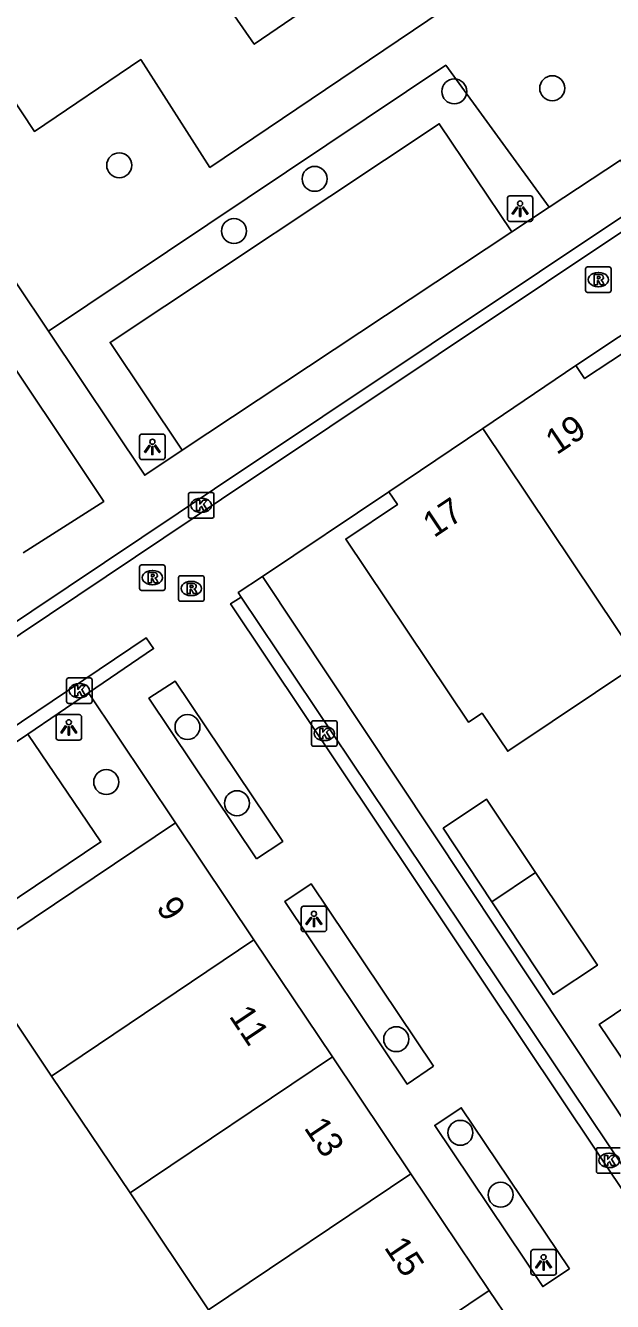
# Model space of a CAD drawing. Extents: x 158797 to 159887, y 384318 to 385255.
# Drawn here: x 159170.3 to 159193.3, y 384529.2 to 384579.2 of the extents above; entities that cross this region are included whole.
import ezdxf

# ---------------------------------------------------------------- set-up
doc = ezdxf.new("R2010")
doc.units = 0
for name, color, linetype in [('IMGEO_Boom', 7, 'Continuous'), ('IMGEO_Groenvoorziening', 7, 'Continuous'), ('IMGEO_Haag', 7, 'Continuous'), ('IMGEO_Kolk', 7, 'Continuous'), ('IMGEO_Lichtpunt', 7, 'Continuous'), ('IMGEO_Pand', 7, 'Continuous'), ('IMGEO_Pand_nummerreeks', 7, 'Continuous'), ('IMGEO_Parkeervlak_open', 7, 'Continuous'), ('IMGEO_Rijbaan_lokaal_open', 7, 'Continuous'), ('IMGEO_Rioolput', 7, 'Continuous'), ('IMGEO_Voetpad_gesloten', 7, 'Continuous'), ('IMGEO_Voetpad_open', 7, 'Continuous')]:
    doc.layers.add(name, color=color, linetype=linetype)

msp = doc.modelspace()

# ---------------------------------------------------------------- linework, layer by layer
at = {"layer": 'IMGEO_Boom'}
for centre in [(159187.135, 384576.663), (159190.976, 384576.789), (159174.003, 384573.767), (159181.664, 384573.236), (159178.503, 384571.191), (159176.68, 384551.749), (159173.494, 384549.591), (159178.62, 384548.763), (159184.861, 384539.513), (159187.378, 384535.843), (159188.951, 384533.417)]:
    msp.add_circle(centre, 0.489, dxfattribs=at)
at = {"layer": 'IMGEO_Groenvoorziening'}
msp.add_lwpolyline([(159179.615, 384557.65), (159196.883, 384531.677)], dxfattribs=at)
at = {"layer": 'IMGEO_Haag'}
msp.add_lwpolyline([(159171.232, 384567.261), (159186.801, 384577.691), (159190.856, 384572.121)], dxfattribs=at)
at = {"layer": 'IMGEO_Kolk'}
for p, q in [((159176.716, 384560.013), (159176.716, 384560.865)), ((159176.791, 384560.939), (159177.643, 384560.939)), ((159177.204, 384560.719), (159177.229, 384560.719)), ((159177.717, 384560.865), (159177.717, 384560.013)), ((159177.227, 384560.159), (159177.202, 384560.159)), ((159177.643, 384559.939), (159176.791, 384559.939)), ((159171.941, 384552.748), (159171.941, 384553.6)), ((159172.016, 384553.674), (159172.868, 384553.674)), ((159172.942, 384553.6), (159172.942, 384552.748)), ((159172.429, 384553.454), (159172.454, 384553.454)), ((159172.868, 384552.674), (159172.016, 384552.674)), ((159172.452, 384552.894), (159172.427, 384552.894)), ((159181.617, 384551.995), (159182.469, 384551.995)), ((159181.542, 384551.069), (159181.542, 384551.921)), ((159182.03, 384551.775), (159182.055, 384551.775)), ((159182.543, 384551.921), (159182.543, 384551.069)), ((159182.469, 384550.995), (159181.617, 384550.995)), ((159182.053, 384551.215), (159182.028, 384551.215)), ((159192.708, 384534.334), (159192.708, 384535.186)), ((159192.783, 384535.26), (159193.635, 384535.26)), ((159193.196, 384535.04), (159193.221, 384535.04)), ((159193.635, 384534.26), (159192.783, 384534.26)), ((159193.219, 384534.48), (159193.194, 384534.48))]:
    msp.add_line(p, q, dxfattribs=at)
for points in [[(159176.716, 384560.013), (159176.716, 384560.865)], [(159176.791, 384560.939), (159177.643, 384560.939)], [(159177.037, 384560.639), (159177.16, 384560.639), (159177.16, 384560.488), (159177.29, 384560.639), (159177.454, 384560.639), (159177.308, 384560.488), (159177.461, 384560.239), (159177.309, 384560.239), (159177.224, 384560.403), (159177.16, 384560.336), (159177.16, 384560.239), (159177.037, 384560.239), (159177.037, 384560.639)], [(159177.717, 384560.865), (159177.717, 384560.013)], [(159177.643, 384559.939), (159176.791, 384559.939)], [(159171.941, 384552.748), (159171.941, 384553.6)], [(159172.016, 384553.674), (159172.868, 384553.674)], [(159172.942, 384553.6), (159172.942, 384552.748)], [(159172.262, 384553.374), (159172.385, 384553.374), (159172.385, 384553.223), (159172.515, 384553.374), (159172.679, 384553.374), (159172.533, 384553.223), (159172.686, 384552.974), (159172.534, 384552.974), (159172.449, 384553.138), (159172.385, 384553.071), (159172.385, 384552.974), (159172.262, 384552.974), (159172.262, 384553.374)], [(159172.868, 384552.674), (159172.016, 384552.674)], [(159181.617, 384551.995), (159182.469, 384551.995)], [(159181.542, 384551.069), (159181.542, 384551.921)], [(159181.863, 384551.695), (159181.986, 384551.695), (159181.986, 384551.544), (159182.116, 384551.695), (159182.28, 384551.695), (159182.134, 384551.544), (159182.287, 384551.295), (159182.135, 384551.295), (159182.05, 384551.459), (159181.986, 384551.392), (159181.986, 384551.295), (159181.863, 384551.295), (159181.863, 384551.695)], [(159182.543, 384551.921), (159182.543, 384551.069)], [(159182.469, 384550.995), (159181.617, 384550.995)], [(159192.708, 384534.334), (159192.708, 384535.186)], [(159192.783, 384535.26), (159193.635, 384535.26)], [(159193.029, 384534.96), (159193.152, 384534.96), (159193.152, 384534.809), (159193.282, 384534.96), (159193.446, 384534.96), (159193.3, 384534.809), (159193.453, 384534.56), (159193.301, 384534.56), (159193.216, 384534.724), (159193.152, 384534.657), (159193.152, 384534.56), (159193.029, 384534.56), (159193.029, 384534.96)], [(159193.635, 384534.26), (159192.783, 384534.26)]]:
    msp.add_lwpolyline(points, dxfattribs=at)
for centre, start, end in [((159176.793, 384560.863), 91.552, 178.448), ((159176.793, 384560.863), 91.552, 178.448), ((159177.641, 384560.863), 1.552, 88.448), ((159177.641, 384560.863), 1.552, 88.448), ((159176.793, 384560.015), 181.552, 268.448), ((159176.793, 384560.015), 181.552, 268.448), ((159177.641, 384560.015), 271.552, 358.448), ((159177.641, 384560.015), 271.552, 358.448), ((159172.018, 384553.598), 91.552, 178.448), ((159172.018, 384553.598), 91.552, 178.448), ((159172.866, 384553.598), 1.552, 88.448), ((159172.866, 384553.598), 1.552, 88.448), ((159172.018, 384552.75), 181.552, 268.448), ((159172.018, 384552.75), 181.552, 268.448), ((159172.866, 384552.75), 271.552, 358.448), ((159172.866, 384552.75), 271.552, 358.448), ((159181.619, 384551.919), 91.552, 178.448), ((159181.619, 384551.919), 91.552, 178.448), ((159182.467, 384551.919), 1.552, 88.448), ((159182.467, 384551.919), 1.552, 88.448), ((159181.619, 384551.071), 181.552, 268.448), ((159181.619, 384551.071), 181.552, 268.448), ((159182.467, 384551.071), 271.552, 358.448), ((159182.467, 384551.071), 271.552, 358.448), ((159192.785, 384535.184), 91.552, 178.448), ((159192.785, 384535.184), 91.552, 178.448), ((159192.785, 384534.336), 181.552, 268.448), ((159192.785, 384534.336), 181.552, 268.448)]:
    msp.add_arc(centre, 0.0765, start, end, dxfattribs=at)
for centre, major_axis, ratio, start_param, end_param in [((159177.203, 384560.439), (-0.387, 0.002), 0.722429, 4.712389, 7.853982), ((159177.228, 384560.439), (-0.39, 0.002), 0.717154, 1.570796, 4.712389), ((159172.428, 384553.174), (-0.387, 0.002), 0.722429, 4.712389, 7.853982), ((159172.453, 384553.174), (-0.39, 0.002), 0.717154, 1.570796, 4.712389), ((159182.029, 384551.495), (-0.387, 0.002), 0.722429, 4.712389, 7.853982), ((159182.054, 384551.495), (-0.39, 0.002), 0.717154, 1.570796, 4.712389), ((159193.195, 384534.76), (-0.387, 0.002), 0.722429, 4.712389, 7.853982), ((159193.22, 384534.76), (-0.39, 0.002), 0.717154, 1.570796, 4.712389)]:
    msp.add_ellipse(centre, major_axis=major_axis, ratio=ratio, start_param=start_param, end_param=end_param, dxfattribs=at)
at = {"layer": 'IMGEO_Lichtpunt'}
for p, q in [((159190.121, 384572.566), (159189.313, 384572.566)), ((159190.121, 384572.566), (159189.313, 384572.566)), ((159189.219, 384572.471), (159189.219, 384571.664)), ((159189.219, 384572.471), (159189.219, 384571.664)), ((159190.215, 384571.664), (159190.215, 384572.471)), ((159190.215, 384571.664), (159190.215, 384572.471)), ((159189.313, 384571.57), (159190.121, 384571.57)), ((159189.313, 384571.57), (159190.121, 384571.57)), ((159174.804, 384563.135), (159174.804, 384562.328)), ((159174.804, 384563.135), (159174.804, 384562.328)), ((159175.706, 384563.23), (159174.898, 384563.23)), ((159175.706, 384563.23), (159174.898, 384563.23)), ((159175.8, 384562.328), (159175.8, 384563.135)), ((159175.8, 384562.328), (159175.8, 384563.135)), ((159174.898, 384562.234), (159175.706, 384562.234)), ((159174.898, 384562.234), (159175.706, 384562.234)), ((159171.531, 384552.139), (159171.531, 384551.332)), ((159171.531, 384552.139), (159171.531, 384551.332)), ((159172.433, 384552.234), (159171.625, 384552.234)), ((159172.433, 384552.234), (159171.625, 384552.234)), ((159172.527, 384551.332), (159172.527, 384552.139)), ((159172.527, 384551.332), (159172.527, 384552.139)), ((159171.625, 384551.238), (159172.433, 384551.238)), ((159171.625, 384551.238), (159172.433, 384551.238)), ((159181.137, 384544.63), (159181.137, 384543.823)), ((159181.137, 384544.63), (159181.137, 384543.823)), ((159182.039, 384544.725), (159181.231, 384544.725)), ((159182.039, 384544.725), (159181.231, 384544.725)), ((159182.133, 384543.823), (159182.133, 384544.63)), ((159182.133, 384543.823), (159182.133, 384544.63)), ((159181.231, 384543.729), (159182.039, 384543.729)), ((159181.231, 384543.729), (159182.039, 384543.729)), ((159190.141, 384531.169), (159190.141, 384530.362)), ((159190.141, 384531.169), (159190.141, 384530.362)), ((159191.043, 384531.264), (159190.235, 384531.264)), ((159191.043, 384531.264), (159190.235, 384531.264)), ((159191.137, 384530.362), (159191.137, 384531.169)), ((159191.137, 384530.362), (159191.137, 384531.169)), ((159190.235, 384530.268), (159191.043, 384530.268)), ((159190.235, 384530.268), (159191.043, 384530.268))]:
    msp.add_line(p, q, dxfattribs=at)
for points in [[(159189.593, 384572.135), (159189.632, 384572.107), (159189.444, 384571.845), (159189.406, 384571.872), (159189.593, 384572.135)], [(159189.695, 384572.087), (159189.742, 384572.087), (159189.742, 384571.765), (159189.695, 384571.765), (159189.695, 384572.087)], [(159189.805, 384572.107), (159189.843, 384572.134), (159190.03, 384571.872), (159189.991, 384571.844), (159189.805, 384572.107)], [(159175.178, 384562.799), (159175.217, 384562.771), (159175.029, 384562.509), (159174.991, 384562.536), (159175.178, 384562.799)], [(159175.28, 384562.751), (159175.327, 384562.751), (159175.327, 384562.429), (159175.28, 384562.429), (159175.28, 384562.751)], [(159175.39, 384562.771), (159175.428, 384562.798), (159175.615, 384562.536), (159175.576, 384562.508), (159175.39, 384562.771)], [(159171.905, 384551.803), (159171.944, 384551.775), (159171.756, 384551.513), (159171.718, 384551.54), (159171.905, 384551.803)], [(159172.007, 384551.755), (159172.054, 384551.755), (159172.054, 384551.433), (159172.007, 384551.433), (159172.007, 384551.755)], [(159172.117, 384551.775), (159172.155, 384551.802), (159172.342, 384551.54), (159172.303, 384551.512), (159172.117, 384551.775)], [(159181.511, 384544.294), (159181.55, 384544.266), (159181.362, 384544.004), (159181.324, 384544.031), (159181.511, 384544.294)], [(159181.613, 384544.246), (159181.66, 384544.246), (159181.66, 384543.924), (159181.613, 384543.924), (159181.613, 384544.246)], [(159181.723, 384544.266), (159181.761, 384544.293), (159181.948, 384544.031), (159181.909, 384544.003), (159181.723, 384544.266)], [(159190.515, 384530.833), (159190.554, 384530.805), (159190.366, 384530.543), (159190.328, 384530.57), (159190.515, 384530.833)], [(159190.617, 384530.785), (159190.664, 384530.785), (159190.664, 384530.463), (159190.617, 384530.463), (159190.617, 384530.785)], [(159190.727, 384530.805), (159190.765, 384530.832), (159190.952, 384530.57), (159190.913, 384530.542), (159190.727, 384530.805)]]:
    msp.add_lwpolyline(points, dxfattribs=at)
for centre in [(159189.718, 384572.269), (159175.303, 384562.933), (159172.03, 384551.937), (159181.636, 384544.428), (159190.64, 384530.967)]:
    msp.add_circle(centre, 0.0994, dxfattribs=at)
for centre, start, end in [((159189.313, 384572.471), 90, 180), ((159189.313, 384572.471), 90, 180), ((159190.121, 384572.471), 0, 90), ((159190.121, 384572.471), 0, 90), ((159189.313, 384571.664), 180, 270), ((159189.313, 384571.664), 180, 270), ((159190.121, 384571.664), 270, 0), ((159190.121, 384571.664), 270, 360), ((159174.898, 384563.135), 90, 180), ((159174.898, 384563.135), 90, 180), ((159175.706, 384563.135), 0, 90), ((159175.706, 384563.135), 0, 90), ((159174.898, 384562.328), 180, 270), ((159174.898, 384562.328), 180, 270), ((159175.706, 384562.328), 270, 0), ((159175.706, 384562.328), 270, 360), ((159171.625, 384552.139), 90, 180), ((159171.625, 384552.139), 90, 180), ((159172.433, 384552.139), 0, 90), ((159172.433, 384552.139), 0, 90), ((159171.625, 384551.332), 180, 270), ((159171.625, 384551.332), 180, 270), ((159172.433, 384551.332), 270, 0), ((159172.433, 384551.332), 270, 360), ((159181.231, 384544.63), 90, 180), ((159181.231, 384544.63), 90, 180), ((159182.039, 384544.63), 0, 90), ((159182.039, 384544.63), 0, 90), ((159181.231, 384543.823), 180, 270), ((159181.231, 384543.823), 180, 270), ((159182.039, 384543.823), 270, 0), ((159182.039, 384543.823), 270, 360), ((159190.235, 384531.169), 90, 180), ((159190.235, 384531.169), 90, 180), ((159191.043, 384531.169), 0, 90), ((159191.043, 384531.169), 0, 90), ((159190.235, 384530.362), 180, 270), ((159190.235, 384530.362), 180, 270), ((159191.043, 384530.362), 270, 0), ((159191.043, 384530.362), 270, 360)]:
    msp.add_arc(centre, 0.0946, start, end, dxfattribs=at)
at = {"layer": 'IMGEO_Pand'}
for points in [[(159191.903, 384565.914), (159192.245, 384565.407), (159194.299, 384566.763), (159199.128, 384559.588), (159198.584, 384559.214), (159199.588, 384557.723), (159194.41, 384554.261)], [(159188.261, 384563.455), (159191.903, 384565.914)], [(159184.571, 384560.964), (159188.261, 384563.455)], [(159188.261, 384563.455), (159194.41, 384554.261)], [(159194.41, 384554.261), (159189.232, 384550.798), (159188.227, 384552.291), (159187.697, 384551.937), (159182.886, 384559.116), (159184.908, 384560.47), (159184.571, 384560.964)], [(159188.609, 384544.902), (159186.705, 384547.782), (159188.395, 384548.922), (159190.315, 384546.05)], [(159168.272, 384542.666), (159176.212, 384547.991)], [(159176.212, 384547.991), (159179.286, 384543.407)], [(159190.315, 384546.05), (159192.747, 384542.412), (159191.013, 384541.266), (159188.609, 384544.902)], [(159190.315, 384546.05), (159188.609, 384544.902)], [(159197.999, 384532.399), (159192.822, 384540.091), (159198.743, 384544.081), (159203.6, 384536.887), (159201.572, 384535.526), (159201.909, 384535.023)], [(159179.286, 384543.407), (159171.356, 384538.068)], [(159179.286, 384543.407), (159182.36, 384538.824)], [(159171.356, 384538.068), (159168.272, 384542.666)], [(159182.36, 384538.824), (159174.43, 384533.484)], [(159182.36, 384538.824), (159185.434, 384534.241)], [(159174.43, 384533.484), (159171.356, 384538.068)], [(159177.505, 384528.901), (159185.434, 384534.241)], [(159185.434, 384534.241), (159188.508, 384529.657)], [(159177.505, 384528.901), (159174.43, 384533.484)], [(159188.508, 384529.657), (159180.569, 384524.332)]]:
    msp.add_lwpolyline(points, dxfattribs=at)
at = {"layer": 'IMGEO_Parkeervlak_open'}
for points in [[(159189.399, 384571.161), (159186.547, 384575.396), (159173.643, 384566.823), (159176.47, 384562.598)], [(159159.576, 384544.176), (159162.426, 384539.948), (159173.284, 384547.242), (159170.423, 384551.464)]]:
    msp.add_lwpolyline(points, dxfattribs=at)
at = {"layer": 'IMGEO_Rijbaan_lokaal_open'}
for points in [[(159195.001, 384572.021), (159178.017, 384560.678), (159131.797, 384529.704), (159111.782, 384559.411)], [(159130.515, 384532.465), (159131.92, 384530.403), (159177.742, 384561.091), (159194.721, 384572.428)], [(159196.883, 384569.224), (159191.903, 384565.914)], [(159184.571, 384560.964), (159179.615, 384557.65)], [(159178.788, 384556.84), (159178.669, 384557.017), (159179.615, 384557.65)], [(159196.033, 384531.127), (159195.59, 384530.821), (159178.371, 384556.579), (159178.788, 384556.84)], [(159196.033, 384531.127), (159178.788, 384556.84)], [(159190.205, 384527.153), (159192.762, 384528.848), (159193.039, 384528.419), (159151.428, 384500.515), (159133.468, 384527.238), (159175.064, 384555.242), (159175.35, 384554.823), (159172.804, 384553.09)], [(159179.385, 384546.576), (159175.165, 384552.881), (159176.194, 384553.55), (159180.411, 384547.264), (159179.385, 384546.576)], [(159172.804, 384553.09), (159170.423, 384551.464)], [(159172.804, 384553.09), (159176.212, 384547.991)], [(159170.423, 384551.464), (159159.576, 384544.176)], [(159186.324, 384538.449), (159185.288, 384537.754), (159180.497, 384544.914), (159181.525, 384545.604), (159186.324, 384538.449)], [(159191.652, 384530.508), (159190.602, 384529.814), (159186.374, 384536.131), (159187.412, 384536.828), (159191.652, 384530.508)], [(159188.508, 384529.657), (159190.205, 384527.153)]]:
    msp.add_lwpolyline(points, dxfattribs=at)
at = {"layer": 'IMGEO_Rioolput'}
for p, q in [((159192.284, 384568.859), (159192.284, 384569.711)), ((159192.359, 384569.785), (159193.211, 384569.785)), ((159192.772, 384569.565), (159192.797, 384569.565)), ((159193.285, 384569.711), (159193.285, 384568.859)), ((159192.795, 384569.005), (159192.77, 384569.005)), ((159193.211, 384568.785), (159192.359, 384568.785)), ((159174.803, 384557.178), (159174.803, 384558.03)), ((159174.878, 384558.104), (159175.73, 384558.104)), ((159175.804, 384558.03), (159175.804, 384557.178)), ((159175.291, 384557.884), (159175.316, 384557.884)), ((159176.328, 384556.753), (159176.328, 384557.605)), ((159176.403, 384557.679), (159177.255, 384557.679)), ((159177.329, 384557.605), (159177.329, 384556.753)), ((159175.73, 384557.104), (159174.878, 384557.104)), ((159175.314, 384557.324), (159175.289, 384557.324)), ((159176.816, 384557.459), (159176.841, 384557.459)), ((159177.255, 384556.679), (159176.403, 384556.679)), ((159176.839, 384556.899), (159176.814, 384556.899))]:
    msp.add_line(p, q, dxfattribs=at)
for points in [[(159192.284, 384568.859), (159192.284, 384569.711)], [(159192.359, 384569.785), (159193.211, 384569.785)], [(159193.285, 384569.711), (159193.285, 384568.859)], [(159192.873, 384569.483), (159192.621, 384569.485), (159192.621, 384569.085)], [(159192.621, 384569.085), (159192.745, 384569.085), (159192.745, 384569.247), (159192.756, 384569.247)], [(159192.799, 384569.404), (159192.745, 384569.404), (159192.745, 384569.323)], [(159192.745, 384569.323), (159192.797, 384569.323)], [(159192.803, 384569.218), (159192.874, 384569.085), (159193.014, 384569.085), (159192.949, 384569.211)], [(159193.211, 384568.785), (159192.359, 384568.785)], [(159174.803, 384557.178), (159174.803, 384558.03)], [(159174.878, 384558.104), (159175.73, 384558.104)], [(159175.804, 384558.03), (159175.804, 384557.178)], [(159175.392, 384557.802), (159175.14, 384557.804), (159175.14, 384557.404)], [(159175.14, 384557.404), (159175.264, 384557.404), (159175.264, 384557.566), (159175.275, 384557.566)], [(159175.318, 384557.723), (159175.264, 384557.723), (159175.264, 384557.642)], [(159175.264, 384557.642), (159175.316, 384557.642)], [(159175.322, 384557.537), (159175.393, 384557.404), (159175.533, 384557.404), (159175.468, 384557.53)], [(159176.328, 384556.753), (159176.328, 384557.605)], [(159176.403, 384557.679), (159177.255, 384557.679)], [(159177.329, 384557.605), (159177.329, 384556.753)], [(159175.73, 384557.104), (159174.878, 384557.104)], [(159176.917, 384557.377), (159176.665, 384557.379), (159176.665, 384556.979)], [(159176.665, 384556.979), (159176.789, 384556.979), (159176.789, 384557.141), (159176.8, 384557.141)], [(159176.843, 384557.298), (159176.789, 384557.298), (159176.789, 384557.217)], [(159176.789, 384557.217), (159176.841, 384557.217)], [(159176.847, 384557.112), (159176.918, 384556.979), (159177.058, 384556.979), (159176.993, 384557.105)], [(159177.255, 384556.679), (159176.403, 384556.679)]]:
    msp.add_lwpolyline(points, dxfattribs=at)
for centre, radius, start, end in [((159192.361, 384569.709), 0.0765, 91.552, 178.448), ((159192.361, 384569.709), 0.0765, 91.552, 178.448), ((159193.209, 384569.709), 0.0765, 1.552, 88.448), ((159193.209, 384569.709), 0.0765, 1.552, 88.448), ((159192.755, 384569.194), 0.0533, 26.0293, 88.6989), ((159192.781, 384569.512), 0.19, 274.7715, 282.9687), ((159192.805, 384569.308), 0.0964, 77.0061, 93.1865), ((159192.819, 384569.365), 0.0378, 276.6634, 79.6772), ((159192.872, 384569.373), 0.109, 350.3612, 89.416), ((159192.87, 384569.373), 0.112, 277.5842, 350.9817), ((159192.854, 384569.158), 0.108, 29.5134, 73.7905), ((159192.361, 384568.861), 0.0765, 181.552, 268.448), ((159192.361, 384568.861), 0.0765, 181.552, 268.448), ((159193.209, 384568.861), 0.0765, 271.552, 358.448), ((159193.209, 384568.861), 0.0765, 271.552, 358.448), ((159174.88, 384558.028), 0.0765, 91.552, 178.448), ((159174.88, 384558.028), 0.0765, 91.552, 178.448), ((159175.728, 384558.028), 0.0765, 1.552, 88.448), ((159175.728, 384558.028), 0.0765, 1.552, 88.448), ((159175.274, 384557.513), 0.0533, 26.0293, 88.6989), ((159175.3, 384557.831), 0.19, 274.7715, 282.9687), ((159175.324, 384557.627), 0.0964, 77.0061, 93.1865), ((159175.338, 384557.684), 0.0378, 276.6634, 79.6772), ((159175.391, 384557.692), 0.109, 350.3612, 89.416), ((159175.389, 384557.692), 0.112, 277.5842, 350.9817), ((159175.373, 384557.477), 0.108, 29.5134, 73.7905), ((159176.405, 384557.603), 0.0765, 91.552, 178.448), ((159176.405, 384557.603), 0.0765, 91.552, 178.448), ((159177.253, 384557.603), 0.0765, 1.552, 88.448), ((159177.253, 384557.603), 0.0765, 1.552, 88.448), ((159174.88, 384557.18), 0.0765, 181.552, 268.448), ((159174.88, 384557.18), 0.0765, 181.552, 268.448), ((159175.728, 384557.18), 0.0765, 271.552, 358.448), ((159175.728, 384557.18), 0.0765, 271.552, 358.448), ((159176.799, 384557.088), 0.0533, 26.0293, 88.6989), ((159176.825, 384557.406), 0.19, 274.7715, 282.9687), ((159176.849, 384557.202), 0.0964, 77.0061, 93.1865), ((159176.863, 384557.259), 0.0378, 276.6634, 79.6772), ((159176.916, 384557.267), 0.109, 350.3612, 89.416), ((159176.914, 384557.267), 0.112, 277.5842, 350.9817), ((159176.898, 384557.052), 0.108, 29.5134, 73.7905), ((159176.405, 384556.755), 0.0765, 181.552, 268.448), ((159176.405, 384556.755), 0.0765, 181.552, 268.448), ((159177.253, 384556.755), 0.0765, 271.552, 358.448), ((159177.253, 384556.755), 0.0765, 271.552, 358.448)]:
    msp.add_arc(centre, radius, start, end, dxfattribs=at)
for centre, major_axis, ratio, start_param, end_param in [((159192.771, 384569.285), (-0.387, 0.002), 0.722429, 4.712389, 7.853982), ((159192.796, 384569.285), (-0.39, 0.002), 0.717154, 1.570796, 4.712389), ((159175.29, 384557.604), (-0.387, 0.002), 0.722429, 4.712389, 7.853982), ((159175.315, 384557.604), (-0.39, 0.002), 0.717154, 1.570796, 4.712389), ((159176.815, 384557.179), (-0.387, 0.002), 0.722429, 4.712389, 7.853982), ((159176.84, 384557.179), (-0.39, 0.002), 0.717154, 1.570796, 4.712389)]:
    msp.add_ellipse(centre, major_axis=major_axis, ratio=ratio, start_param=start_param, end_param=end_param, dxfattribs=at)
at = {"layer": 'IMGEO_Voetpad_gesloten'}
for points in [[(159139.375, 384579.667), (159141.123, 384576.932), (159150.625, 384583.433), (159151.747, 384581.759), (159165.041, 384590.724), (159170.605, 384582.437), (159174.689, 384585.159), (159179.297, 384578.512), (159193.347, 384588.107), (159197.808, 384581.483), (159198.988, 384582.307), (159199.249, 384581.925), (159200.917, 384582.98), (159201.158, 384582.618), (159202.847, 384583.73)], [(159193.8, 384573.756), (159197.584, 384576.354), (159193.706, 384582.105), (159191.156, 384580.471), (159190.067, 384582.131), (159177.557, 384573.685), (159174.848, 384577.908), (159170.678, 384575.093), (159165.114, 384583.512), (159164.29, 384582.941), (159163.188, 384584.508), (159154.051, 384578.453), (159155.852, 384575.778)]]:
    msp.add_lwpolyline(points, dxfattribs=at)
at = {"layer": 'IMGEO_Voetpad_open'}
for points in [[(159171.232, 384567.261), (159162.529, 384580.264), (159155.852, 384575.778)], [(159193.8, 384573.756), (159193.655, 384573.965), (159190.856, 384572.121)], [(159190.856, 384572.121), (159189.399, 384571.161)], [(159189.399, 384571.161), (159176.47, 384562.598)], [(159170.24, 384558.583), (159173.398, 384560.595), (159168.665, 384567.656)], [(159176.47, 384562.598), (159175.007, 384561.62), (159171.232, 384567.261)]]:
    msp.add_lwpolyline(points, dxfattribs=at)

# ---------------------------------------------------------------- texts
at = {"layer": 'IMGEO_Pand_nummerreeks'}
for s, rotation, p in [('19', 33.8274, (159191.151, 384562.394)), ('17', 33.8274, (159186.341, 384559.146)), ('9', 303.8505, (159175.426, 384544.675)), ('11', 303.8505, (159178.282, 384540.416)), ('13', 303.8505, (159181.221, 384536.035)), ('15', 303.8505, (159184.363, 384531.35))]:
    msp.add_text(s, height=1, rotation=rotation, dxfattribs=at).set_placement(p)

doc.saveas('drawing.dxf')
